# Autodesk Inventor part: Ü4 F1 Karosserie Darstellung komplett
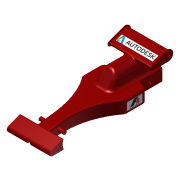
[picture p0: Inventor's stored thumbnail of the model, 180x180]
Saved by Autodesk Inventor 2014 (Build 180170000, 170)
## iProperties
Created: 2013-07
Part Number: Ü4 F1 Karosserie Darstellung komplett
Material: Generisch
Document SubType Name: Modeling
Designer: Sofia
Density: 1 g/cm^3
Appearance: Rot
Author: Sofia
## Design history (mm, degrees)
sketch "Skizze1"
  geometry: L1 (0, 0)-(200, 0); L2 (200, 0)-(200, 20); L3 (200, 20)-(110, 20); L4 (0, 8)-(0, 0); A1 r 510.167 centre (110, -490.167) between (110, 20) and (0, 8)
  constraints: 8 end point, 2 perpendicular, 2 point on circle, 1 centre point, 1 horizontal, 1 parallel, 1 tangent
  dimensions: "d2" = 200 distance of L1.start L1.end; "d3" = 20 distance of L1.end L2.end; "d4" = 90 distance of L2.end L3.end; "d5" = 8 distance of L4.start L1.start
extrude "Extrusion1" new body sketch "Skizze1" distance "d6" = 35; taper "d7" = 0 deg
sketch "Skizze2"
  geometry: L1 (0, 0)-(200, 0) reference; L2 (0, 35)-(200, 35) reference; L3 (0, 0)-(0, 35) reference; L4 (0, 10)-(50, 10); L5 (200, 35)-(160, 35); L6 (160, 35)-(160, 19); L7 (160, 19)-(200, 19); L8 (200, 19)-(200, 35); A1 r 120 centre (50, 130) between (50, 10) and (123.314, 35)
  constraints: 10 end point, 2 parallel, 2 perpendicular, 2 point on circle, 2 point on line, 1 centre point, 1 horizontal, 1 tangent
  dimensions: "d8" = 50 distance of L4.start L4.end; "d9" = 10 distance between parallel lines of L4 L1; "d10" = 120 radius of A1; "d13" = 40 distance of L7.end L6.end; "d14" = 16 distance of L6.end L5.end
extrude "Extrusion2" cut sketch "Skizze2" stored distance "d15" = 35; taper "d16" = 0 deg
sketch "Skizze3"
  geometry: L1 (0, 0)-(0, 8) reference; L2 (50, 0)-(0, 0) reference; C1 r 3 at (40, 8)
  constraints: 1 centre point
  dimensions: "d17" = 6 diameter of C1; "d18" = 8 distance from line of C1.centre L2; "d19" = 40 distance from line of C1.centre L1
extrude "Extrusion3" join sketch "Skizze3" distance "d20" = 10; taper "d21" = 0 deg
hole "Bohrung1" diameter "d24" = 3; stored, may be unused: countersink angle "d28" = 90 deg, drill point angle "d30" = 118 deg; dims "d22" = 10, "d23" = 10, "d25" = 6, "d26" = 4, "d27" = 2, "d29" = 8
pattern_linear "Rechteckige Anordnung1"
fillet "Rundung1" dims "d34" = 8
mirror "Spiegeln1"
sketch "Skizze4"
  geometry: L1 (38, 0)-(0, 0) reference; L2 (38, 20)-(0, 20) reference; L3 (5, 20)-(5, 30); L4 (33, 30)-(33, 20); A1 r 14 centre (19, 30) between (33, 30) and (5, 30); 2 further points
  constraints: 4 end point, 2 perpendicular, 2 point on circle, 2 point on line, 2 tangent, 1 centre point, 1 midpoint, 1 vertical alignment
  dimensions: "d35" = 14 radius of A1; "d36" = 30 distance from line of A1.centre L1
extrude "Extrusion4" join sketch "Skizze4" distance "d37" = 80; taper "d38" = 0 deg
sketch "Skizze5"
  geometry: L1 (200, 0)-(0, 0) reference; L2 (0, 0)-(0, 8) reference; L3 (110, 20)-(120, 20) reference; L4 (120, 20)-(120, 44) reference; L5 (120, 44)-(200, 44) reference; L6 (200, 44)-(200, 0) reference; L7 (25.066, 17.123)-(0, 8); L8 (168.592, 41)-(193.592, 41); L9 (191.4, 53.43)-(167.908, 44.879); C1 r 1.5 at (180, 8) reference; C2 r 1.5 at (40, 8) reference; A1 r 510.167 centre (110, -490.167) between (110, 20) and (0, 8) reference; A2 r 17.5 centre (40, 8) between (25.066, 17.123) and (24.436, 0); A3 r 6.408 centre (193.592, 47.408) between (193.592, 41) and (191.4, 53.43); A4 r 2 centre (168.592, 43) between (167.908, 44.879) and (168.592, 41)
  constraints: 6 end point, 6 point on circle, 5 tangent, 3 centre point, 1 coincident, 1 perpendicular, 1 point on line
  dimensions: "d39" = 17.5 radius of A2; "d40" = 20 deg angle of L1 L7; "d41" = 20 deg angle of L8 L9; "d42" = 2 radius of A4; "d43" = 25 distance of L8.start L8.end; "d44" = 3 distance between parallel lines of L5 L8
  node "Schnittkanten projizieren1"
extrude "Extrusion5" join sketch "Skizze5" stored distance "d45" = 70; taper "d46" = 0 deg
extrude "Extrusion6" join sketch "Skizze5" stored distance "d47" = 70; taper "d48" = 0 deg
hole "Bohrung2" diameter "d51" = 19.5; stored, may be unused: countersink angle "d55" = 90 deg, drill point angle "d57" = 118 deg; dims "d49" = 10, "d50" = 10, "d52" = 6, "d53" = 4, "d54" = 2, "d56" = 55
sketch "Skizze6"
  geometry: L1 (200, 0)-(0, 0) reference; L2 (0, 0)-(0, 8) reference; L3 (0, 8)-(25.066, 17.123) reference; L4 (110, 20)-(120, 20) reference; L5 (120, 20)-(120, 44) reference; L6 (120, 44)-(166.86, 44) reference; L7 (167.908, 44.879)-(191.4, 53.43) reference; L8 (199.019, 44)-(200, 44) reference; L9 (200, 44)-(200, 39.75) reference; L10 (200, 39.75)-(145, 39.75) reference; L11 (145, 39.75)-(139.142, 30) reference; L12 (139.142, 30)-(145, 20.25) reference; L13 (145, 20.25)-(200, 20.25) reference; L14 (200, 20.25)-(200, 0) reference; L15 (120, 20)-(133.856, 44); C1 r 1.5 at (180, 8) reference; C2 r 1.5 at (40, 8) reference; A1 r 17.5 centre (40, 8) between (25.066, 17.123) and (23.1, 12.544) reference; A2 r 510.167 centre (110, -490.167) between (110, 20) and (23.1, 12.544) reference; A3 r 2 centre (168.592, 43) between (167.908, 44.879) and (166.86, 44) reference; A4 r 6.408 centre (193.592, 47.408) between (199.019, 44) and (191.4, 53.43) reference
  constraints: 2 end point, 1 point on line
  dimensions: "d58" = 30 deg angle of L5 L15
extrude "Extrusion7" cut sketch "Skizze6" stored distance "d59" = 10; taper "d60" = 0 deg
sketch "Skizze7"
  geometry: L1 (168.592, 41)-(193.592, 41) reference; L2 (191.4, 53.43)-(167.908, 44.879) reference; L3 (167.224, 46.759)-(190.716, 55.309); L4 (193.592, 39)-(168.592, 39); A1 r 6.408 centre (193.592, 47.408) between (193.592, 41) and (191.4, 53.43) reference; A2 r 2 centre (168.592, 43) between (167.908, 44.879) and (168.592, 41) reference; A3 r 8.408 centre (193.592, 47.408) between (193.592, 39) and (190.716, 55.309); A4 r 4 centre (168.592, 43) between (167.224, 46.759) and (168.592, 39); 1 further point
  constraints: 4 end point, 4 point on circle, 2 centre point, 3 other
  dimensions: "d61" = 2 distance between parallel lines of L3 L2
extrude "Extrusion8" join sketch "Skizze7" distance "d62" = 1; taper "d63" = 0 deg
mirror "Spiegeln2"
fillet "Rundung2"
fillet "Rundung3" dims "d64" = 2
fillet "Rundung4" dims "d65" = 7
sketch "Skizze8"
  geometry: L1 (38, 0)-(0, 0) reference; L2 (16, 6)-(22, 6); L3 (22, 6)-(22, 0); L4 (22, 0)-(16, 0); L5 (16, 0)-(16, 6); 2 further points
  constraints: 8 end point, 2 midpoint, 2 parallel, 1 horizontal, 1 perpendicular
  dimensions: "d66" = 6 distance of L3.end L4.end; "d67" = 6 distance of L2.end L3.end
extrude "Extrusion9" cut sketch "Skizze8" stored distance "d68" = 1; taper "d69" = 0 deg
sketch "Skizze9"
  geometry: L1 (25, 68)-(25, 0) reference; L2 (16.2, 64)-(16.2, 4); L3 (16.2, 4)-(5.924, 4); L4 (5.924, 4)-(5.924, 64); L5 (5.924, 64)-(16.2, 64); L6 (-0.684, 68)-(22.808, 68) reference; 5 further points; 1 other entity
  constraints: 4 midpoint, 1 horizontal alignment, 1 vertical, 1 vertical alignment, 2 other
  dimensions: "d72" = 60 distance of L2.start L2.end
feature "Aufkleber1" sketch "Skizze9"
sketch "Skizze10"
  geometry: L1 (125.993, 18)-(152, 18) reference; L2 (125.993, 0)-(125.993, 18) reference; L3 (126.497, 15.308)-(151.497, 15.308); L4 (151.497, 15.308)-(151.497, 2.692); L5 (151.497, 2.692)-(126.497, 2.692); L6 (126.497, 2.692)-(126.497, 15.308); 5 further points; 1 other entity
  constraints: 4 midpoint, 1 horizontal alignment, 1 vertical alignment, 2 other
  dimensions: "d78" = 25 distance of L4.end L5.end
feature "Aufkleber2" sketch "Skizze10"
sketch "Skizze11"
  geometry: L1 (0, 18)-(26.007, 18) reference; L2 (0, 18)-(0, 0) reference; L3 (0.503, 15.308)-(25.503, 15.308); L4 (25.503, 15.308)-(25.503, 2.692); L5 (25.503, 2.692)-(0.503, 2.692); L6 (0.503, 2.692)-(0.503, 15.308); 5 further points; 1 other entity
  constraints: 4 midpoint, 1 horizontal alignment, 1 vertical alignment, 2 other
  dimensions: "d85" = 25 distance of L3.start L3.end
feature "Aufkleber3" sketch "Skizze11"
node "Volumenkörper1"
node "Bild1"
node "Bild2"
node "Bild3"
node "Schnittkanten projizieren2"
